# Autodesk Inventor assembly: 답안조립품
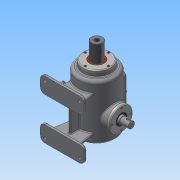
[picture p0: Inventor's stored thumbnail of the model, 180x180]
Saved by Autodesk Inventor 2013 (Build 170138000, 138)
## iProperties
Created: 2016-06
Part Number: 답안조립품
Document SubType Name: Assembly
Designer: Administrator
Mass: 8192.43 g
Surface Area: 4241.77 cm^2
Volume: 1855.48 cm^3
Density: 4.41526 g/cm^3
Author: Administrator
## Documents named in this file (15)
- C:\Users\Administrator\Desktop\Manufacturing1급-김민서\공용부품\답안조립품.iam
- C:\Users\Administrator\Desktop\Manufacturing1급-김민서\공용부품\본체.ipt
- C:\Users\Administrator\Desktop\Manufacturing1급-김민서\공용부품\슬라이드.ipt
- C:\Users\Administrator\Desktop\Manufacturing1급-김민서\공용부품\가변스프링.ipt
- C:\Users\Administrator\Desktop\Manufacturing1급-김민서\공용부품\부시.ipt
- C:\Users\Administrator\Desktop\Manufacturing1급-김민서\공용부품\슬라이드 커버.ipt
- C:\Users\Administrator\Desktop\Manufacturing1급-김민서\공용부품\볼트 M4x0.7.ipt
- C:\Users\Administrator\Desktop\Manufacturing1급-김민서\공용부품\베어링 6205.ipt
- 베어링 6205.ipt
- C:\Users\Administrator\Desktop\Manufacturing1급-김민서\공용부품\축 커버.ipt
- C:\Users\Administrator\Desktop\Manufacturing1급-김민서\공용부품\오일실.ipt
- 오일실.ipt
- C:\Users\Administrator\Desktop\Manufacturing1급-김민서\공용부품\편심축.ipt
- C:\Users\Administrator\Desktop\Manufacturing1급-김민서\공용부품\육각머리볼트 M4.ipt
- C:\Users\Administrator\Desktop\Manufacturing1급-김민서\공용부품\상부커버.ipt
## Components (13 placed, 2 different names)
1. 가변스프링:1 — 각도:6
2. M4x0.7:1
3. M4x0.7:3
4. M4x0.7:4
5. M4x0.7:5
6. M4x0.7:9
7. M4x0.7:2
8. M4x0.7:10
9. M4x0.7:11
10. M4x0.7:12
11. M4x0.7:13
12. M4x0.7:14
13. M4x0.7:15
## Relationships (1: Angle 1)
- 각도:6 [Angle]: 가변스프링:1
